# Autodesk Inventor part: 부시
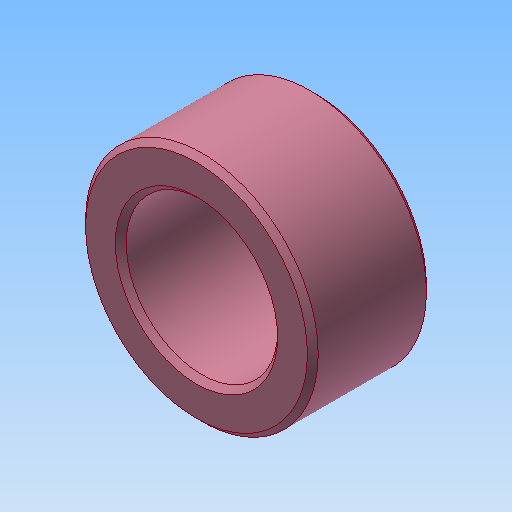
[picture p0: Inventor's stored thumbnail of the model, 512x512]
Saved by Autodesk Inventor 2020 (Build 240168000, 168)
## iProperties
Created: 2010-12
Part Number: 부시
Document SubType Name: Modeling
Designer: 진현석
Density: 1 g/cm^3
Material: 강철, 연강
Appearance: 기본값(1)
Author: 진현석
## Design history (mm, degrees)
sketch "스케치1"
  geometry: C1 r 21.5 at (0, 0) reference; C2 r 31 at (0, 0) reference; C3 r 14 at (0, 0) reference; 1 further point
extrude "돌출1" new body sketch "스케치1" distance "d0" = 22; taper "d1" = 0 deg
chamfer "모따기1" distance "d2" = 1; stored, may be unused: second distance "d3" = 2, angle "d4" = 45 deg
node "솔리드1"
node "참조1"
node "참조2"
